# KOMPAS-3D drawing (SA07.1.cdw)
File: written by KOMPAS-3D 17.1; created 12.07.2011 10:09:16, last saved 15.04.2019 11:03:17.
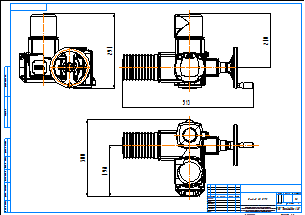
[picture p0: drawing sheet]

Title block, sheet 1: name: Привод SA 07.1; material: Внимание! Данный продукт является объектом авторского права ООО «Торговый Дом АДЛ». / Запрещается изменение, копирование, распространение / (в том числе путем копирования на другие сайты и ресурсы в Интернете) / или любое иное использование информации и объектов без предварительного / согласия правообладателя (ООО «Торговый Дом АДЛ»).; scale: 1:2; sheets: 1; organisation: ООО "Торговый дом АДЛ"; sheet format: A2; stored path: \\adlc.lan\data\АДЛ_ПКД\3D-модели\Поставщики\Сервоприводы AUMA\Электроприводы серии SA\KOMPAS 2D\Привод SA 07.1.cdw

Views: Проекционный вид 2, Проекционный вид 4, Проекционный вид 6
Dimensions and other numbers on the sheet: 300; 198; 291; 513; 210; 1:2; 1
